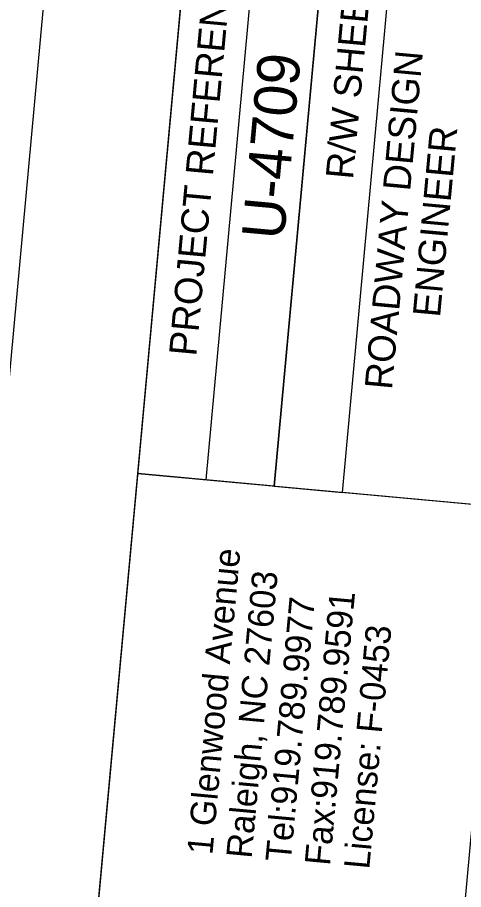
# Model space of a CAD drawing. Extents: x 2012234 to 2013485, y 445879 to 447846.
# Drawn here: x 2012372.3 to 2012453.8, y 447543.6 to 447702.9 of the extents above; entities that cross this region are included whole.
import ezdxf

# ---------------------------------------------------------------- set-up
doc = ezdxf.new("R2010")
doc.units = 0
for name, color, linetype in [('Old_Level_2', 7, 'Continuous'), ('Old_Level_58', 7, 'Continuous'), ('Sheet Data Field CELL', 7, 'Continuous'), ('Sheet Plan And Profile CELL', 7, 'Continuous'), ('Sheet Plot Border Outside CELL', 7, 'Continuous')]:
    doc.layers.add(name, color=color, linetype=linetype)

msp = doc.modelspace()

# ---------------------------------------------------------------- linework, layer by layer
at = {"layer": 'Old_Level_58'}
msp.add_lwpolyline([(2012375.92, 447420.36), (2012394.24, 447619.57), (2012460.65, 447613.46), (2012442.33, 447414.25)], close=True, dxfattribs=at)
at = {"layer": 'Sheet Plan And Profile CELL'}
for p, q in [((2012406.74, 447618.42), (2012425.05, 447817.63)), ((2012419.18, 447617.27), (2012437.5, 447816.48)), ((2012419.18, 447617.27), (2012431.63, 447616.13)), ((2012419.18, 447617.27), (2012431.63, 447616.13))]:
    msp.add_line(p, q, dxfattribs=at)
for points in [[(2012412.56, 447818.78), (2012275.22, 446325.08), (2013320.81, 446228.94), (2013458.14, 447722.64)], [(2012394.24, 447619.57), (2012412.56, 447818.78), (2012437.5, 447816.48), (2012419.18, 447617.27)], [(2012431.63, 447616.13), (2012440.79, 447715.76), (2012552.82, 447705.46), (2012543.66, 447605.83)]]:
    msp.add_lwpolyline(points, close=True, dxfattribs=at)
at = {"layer": 'Sheet Plot Border Outside CELL'}
msp.add_lwpolyline([(2013329.68, 446052.39), (2013485.33, 447745.24), (2012389.95, 447845.96), (2012234.3, 446153.1)], close=True, dxfattribs=at)

# ---------------------------------------------------------------- texts
at = {"layer": 'Old_Level_2'}
for s, p in [('1 Glenwood Avenue', (2012407.88, 447549.82)), ('Raleigh, NC 27603', (2012415.04, 447549.16)), ('Fax:919.789.9591', (2012429.37, 447547.85)), ('Tel:919.789.9977 ', (2012422.21, 447548.51)), ('License: F-0453', (2012436.54, 447547.19))]:
    msp.add_text(s, height=4.6576, rotation=84.7467, dxfattribs=at).set_placement(p)
at = {"layer": 'Sheet Data Field CELL'}
msp.add_text('U-4709', height=7.75, rotation=84.7467, dxfattribs=at).set_placement((2012420.95, 447662.1))
at = {"layer": 'Sheet Plan And Profile CELL'}
for s, height, p in [('PROJECT REFERENCE NO.', 5.0001, (2012404.93, 447640.88)), ('R/W SHEET NO.', 5.0001, (2012433.56, 447673.19)), ('ROADWAY DESIGN', 5.0001, (2012440.68, 447634.78)), ('ENGINEER', 5, (2012449.47, 447647.98))]:
    msp.add_text(s, height=height, rotation=84.7467, dxfattribs=at).set_placement(p)

doc.saveas('drawing.dxf')
